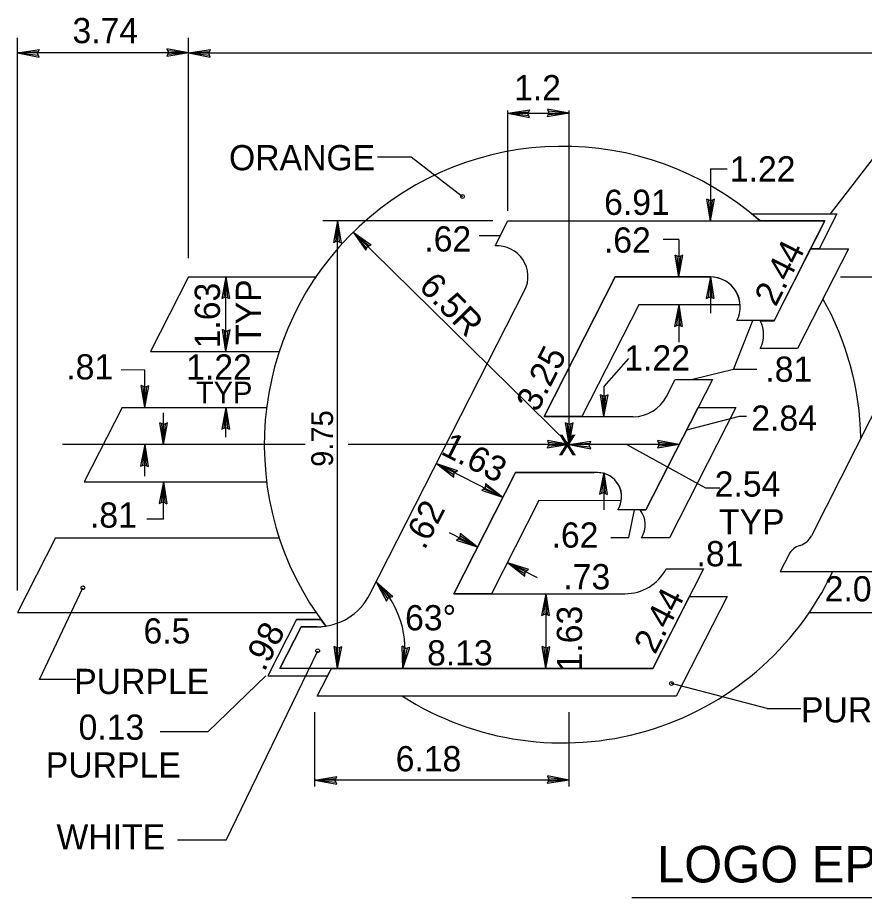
# Model space of a CAD drawing. Extents: x 10268197 to 10269179, y 2141503 to 2142677.
# Drawn here: x 10268592.24 to 10268612.19, y 2142145.29 to 2142166.03 of the extents above; entities that cross this region are included whole.
import ezdxf

# ---------------------------------------------------------------- set-up
doc = ezdxf.new("R2010")
doc.units = 0
for name, color, linetype in [('1', 7, 'Continuous'), ('21', 7, 'Continuous'), ('Default', 7, 'Continuous')]:
    doc.layers.add(name, color=color, linetype=linetype)

msp = doc.modelspace()

# ---------------------------------------------------------------- linework, layer by layer
at = {"layer": '1'}
for p, q in [((10268592.239, 2142152.526), (10268592.239, 2142165.546)), ((10268596.269, 2142160.355), (10268596.269, 2142165.546)), ((10268596.269, 2142165.194), (10268596.782, 2142165.276)), ((10268596.742, 2142165.186), (10268596.782, 2142165.276)), ((10268596.269, 2142165.194), (10268592.239, 2142165.194)), ((10268596.269, 2142165.194), (10268596.761, 2142165.229)), ((10268596.269, 2142165.194), (10268617.622, 2142165.194)), ((10268596.269, 2142165.194), (10268596.779, 2142165.095)), ((10268596.269, 2142165.194), (10268596.76, 2142165.143)), ((10268596.779, 2142165.095), (10268596.742, 2142165.186)), ((10268603.79, 2142163.772), (10268604.305, 2142163.853)), ((10268603.79, 2142161.475), (10268603.79, 2142163.833)), ((10268603.79, 2142163.772), (10268604.283, 2142163.806)), ((10268604.264, 2142163.764), (10268604.305, 2142163.853)), ((10268605.232, 2142155.962), (10268605.232, 2142163.833)), ((10268603.79, 2142163.772), (10268605.232, 2142163.772)), ((10268603.79, 2142163.772), (10268604.301, 2142163.673)), ((10268603.79, 2142163.772), (10268604.282, 2142163.721)), ((10268604.301, 2142163.673), (10268604.264, 2142163.764)), ((10268611.389, 2142161.404), (10268613.109, 2142163.626)), ((10268600.715, 2142162.745), (10268601.51, 2142162.745)), ((10268601.51, 2142162.745), (10268602.722, 2142161.81)), ((10268608.561, 2142162.465), (10268608.561, 2142161.234)), ((10268608.561, 2142162.465), (10268608.959, 2142162.465)), ((10268608.561, 2142161.234), (10268608.48, 2142161.748)), ((10268608.57, 2142161.707), (10268608.48, 2142161.748)), ((10268608.561, 2142161.234), (10268608.527, 2142161.726)), ((10268608.561, 2142161.234), (10268608.661, 2142161.744)), ((10268608.561, 2142161.234), (10268608.613, 2142161.725)), ((10268608.661, 2142161.744), (10268608.57, 2142161.707)), ((10268603.439, 2142161.234), (10268599.428, 2142161.234)), ((10268599.779, 2142161.234), (10268599.68, 2142160.723)), ((10268599.779, 2142161.234), (10268599.728, 2142160.743)), ((10268599.779, 2142150.689), (10268599.779, 2142161.234)), ((10268599.779, 2142161.234), (10268599.86, 2142160.72)), ((10268599.779, 2142161.234), (10268599.813, 2142160.742)), ((10268605.232, 2142155.962), (10268600.148, 2142160.97)), ((10268600.148, 2142160.97), (10268600.571, 2142160.667)), ((10268600.148, 2142160.97), (10268600.443, 2142160.541)), ((10268600.148, 2142160.97), (10268600.462, 2142160.588)), ((10268600.148, 2142160.97), (10268600.523, 2142160.649)), ((10268603.611, 2142160.882), (10268603.111, 2142160.882)), ((10268599.68, 2142160.723), (10268599.771, 2142160.761)), ((10268599.771, 2142160.761), (10268599.86, 2142160.72)), ((10268607.815, 2142160.794), (10268607.45, 2142160.794)), ((10268607.815, 2142160.794), (10268607.815, 2142159.916)), ((10268600.443, 2142160.541), (10268600.48, 2142160.632)), ((10268600.48, 2142160.632), (10268600.571, 2142160.667)), ((10268610.061, 2142158.883), (10268610.924, 2142160.575)), ((10268611.812, 2142160.575), (10268610.614, 2142158.226)), ((10268610.924, 2142160.575), (10268611.812, 2142160.575)), ((10268607.815, 2142159.916), (10268607.733, 2142160.429)), ((10268607.823, 2142160.389), (10268607.733, 2142160.429)), ((10268607.815, 2142159.916), (10268607.781, 2142160.408)), ((10268607.815, 2142159.916), (10268607.914, 2142160.426)), ((10268607.815, 2142159.916), (10268607.866, 2142160.406)), ((10268607.914, 2142160.426), (10268607.823, 2142160.389)), ((10268597.147, 2142159.916), (10268597.048, 2142159.405)), ((10268597.147, 2142159.916), (10268597.096, 2142159.424)), ((10268597.147, 2142158.158), (10268597.147, 2142159.916)), ((10268597.147, 2142159.916), (10268597.229, 2142159.402)), ((10268597.147, 2142159.916), (10268597.182, 2142159.424)), ((10268604.643, 2142156.621), (10268606.322, 2142159.916)), ((10268606.322, 2142159.916), (10268608.561, 2142159.916)), ((10268608.561, 2142159.916), (10268608.462, 2142159.405)), ((10268608.561, 2142159.916), (10268608.51, 2142159.424)), ((10268608.561, 2142159.916), (10268608.643, 2142159.402)), ((10268608.561, 2142159.916), (10268608.596, 2142159.424)), ((10268608.561, 2142159.916), (10268608.561, 2142159.057)), ((10268597.048, 2142159.405), (10268597.139, 2142159.442)), ((10268597.139, 2142159.442), (10268597.229, 2142159.402)), ((10268608.462, 2142159.405), (10268608.553, 2142159.442)), ((10268608.553, 2142159.442), (10268608.643, 2142159.402)), ((10268606.874, 2142159.257), (10268605.531, 2142156.621)), ((10268609.263, 2142159.257), (10268606.874, 2142159.257)), ((10268607.815, 2142159.257), (10268607.716, 2142158.746)), ((10268607.815, 2142159.257), (10268607.764, 2142158.766)), ((10268607.815, 2142159.257), (10268607.815, 2142158.378)), ((10268607.815, 2142159.257), (10268607.897, 2142158.743)), ((10268607.815, 2142159.257), (10268607.85, 2142158.765)), ((10268609.109, 2142157.735), (10268609.56, 2142158.885)), ((10268609.735, 2142158.883), (10268610.061, 2142158.883)), ((10268597.147, 2142158.158), (10268597.066, 2142158.672)), ((10268597.155, 2142158.631), (10268597.066, 2142158.672)), ((10268597.147, 2142158.158), (10268597.112, 2142158.65)), ((10268597.147, 2142158.158), (10268597.247, 2142158.669)), ((10268597.147, 2142158.158), (10268597.199, 2142158.649)), ((10268597.247, 2142158.669), (10268597.155, 2142158.631)), ((10268607.716, 2142158.746), (10268607.807, 2142158.783)), ((10268607.807, 2142158.783), (10268607.897, 2142158.743)), ((10268610.614, 2142158.226), (10268609.735, 2142158.226)), ((10268606.63, 2142157.989), (10268606.051, 2142157.335)), ((10268595.236, 2142157.719), (10268594.679, 2142157.723)), ((10268595.236, 2142156.84), (10268595.236, 2142157.719)), ((10268609.109, 2142157.735), (10268608.142, 2142157.499)), ((10268609.655, 2142157.735), (10268609.109, 2142157.735)), ((10268595.236, 2142156.84), (10268595.154, 2142157.354)), ((10268595.244, 2142157.313), (10268595.154, 2142157.354)), ((10268595.236, 2142156.84), (10268595.201, 2142157.333)), ((10268595.236, 2142156.84), (10268595.335, 2142157.351)), ((10268595.236, 2142156.84), (10268595.287, 2142157.331)), ((10268595.335, 2142157.351), (10268595.244, 2142157.313)), ((10268606.051, 2142157.335), (10268606.051, 2142156.621)), ((10268606.051, 2142156.621), (10268605.969, 2142157.134)), ((10268606.059, 2142157.093), (10268605.969, 2142157.134)), ((10268606.051, 2142156.621), (10268606.016, 2142157.113)), ((10268606.051, 2142156.621), (10268606.15, 2142157.132)), ((10268606.051, 2142156.621), (10268606.102, 2142157.111)), ((10268606.15, 2142157.132), (10268606.059, 2142157.093)), ((10268597.147, 2142156.84), (10268597.048, 2142156.33)), ((10268597.147, 2142156.84), (10268597.096, 2142156.349)), ((10268597.147, 2142156.137), (10268597.147, 2142156.84)), ((10268597.147, 2142156.84), (10268597.229, 2142156.326)), ((10268597.147, 2142156.84), (10268597.182, 2142156.348)), ((10268607.043, 2142154.424), (10268608.274, 2142156.84)), ((10268609.161, 2142156.84), (10268607.595, 2142153.765)), ((10268608.274, 2142156.84), (10268609.161, 2142156.84)), ((10268595.675, 2142155.962), (10268595.675, 2142156.708)), ((10268605.531, 2142156.621), (10268604.643, 2142156.621)), ((10268609.24, 2142156.621), (10268607.999, 2142156.299)), ((10268609.415, 2142156.621), (10268609.24, 2142156.621)), ((10268595.675, 2142155.962), (10268595.594, 2142156.475)), ((10268595.683, 2142156.435), (10268595.594, 2142156.475)), ((10268595.675, 2142155.962), (10268595.641, 2142156.453)), ((10268595.675, 2142155.962), (10268595.774, 2142156.472)), ((10268595.675, 2142155.962), (10268595.726, 2142156.452)), ((10268595.774, 2142156.472), (10268595.683, 2142156.435)), ((10268597.048, 2142156.33), (10268597.139, 2142156.367)), ((10268597.139, 2142156.367), (10268597.229, 2142156.326)), ((10268605.232, 2142155.962), (10268605.15, 2142156.475)), ((10268605.24, 2142156.435), (10268605.15, 2142156.475)), ((10268605.232, 2142155.962), (10268605.197, 2142156.453)), ((10268605.232, 2142155.962), (10268605.33, 2142156.472)), ((10268605.232, 2142155.962), (10268605.283, 2142156.452)), ((10268605.33, 2142156.472), (10268605.24, 2142156.435)), ((10268599.012, 2142155.962), (10268593.295, 2142155.962)), ((10268595.236, 2142155.962), (10268595.137, 2142155.451)), ((10268595.236, 2142155.962), (10268595.184, 2142155.471)), ((10268595.236, 2142155.215), (10268595.236, 2142155.962)), ((10268595.236, 2142155.962), (10268595.317, 2142155.448)), ((10268595.236, 2142155.962), (10268595.27, 2142155.469)), ((10268605.232, 2142155.962), (10268600.025, 2142155.962)), ((10268604.758, 2142155.97), (10268604.717, 2142155.88)), ((10268605.232, 2142155.962), (10268604.717, 2142155.88)), ((10268605.232, 2142155.962), (10268604.721, 2142156.061)), ((10268604.721, 2142156.061), (10268604.758, 2142155.97)), ((10268605.232, 2142155.962), (10268604.74, 2142155.927)), ((10268605.232, 2142155.962), (10268604.741, 2142156.013)), ((10268605.232, 2142155.962), (10268605.745, 2142156.043)), ((10268605.232, 2142155.962), (10268605.724, 2142155.996)), ((10268607.827, 2142155.962), (10268605.232, 2142155.962)), ((10268605.232, 2142155.962), (10268605.742, 2142155.863)), ((10268605.232, 2142155.962), (10268605.722, 2142155.91)), ((10268605.704, 2142155.954), (10268605.745, 2142156.043)), ((10268605.742, 2142155.863), (10268605.704, 2142155.954)), ((10268608.454, 2142154.939), (10268606.584, 2142155.962)), ((10268607.353, 2142155.97), (10268607.313, 2142155.88)), ((10268607.827, 2142155.962), (10268607.313, 2142155.88)), ((10268607.827, 2142155.962), (10268607.316, 2142156.061)), ((10268607.316, 2142156.061), (10268607.353, 2142155.97)), ((10268607.827, 2142155.962), (10268607.334, 2142155.927)), ((10268607.827, 2142155.962), (10268607.335, 2142156.013)), ((10268595.137, 2142155.451), (10268595.228, 2142155.489)), ((10268595.228, 2142155.489), (10268595.317, 2142155.448)), ((10268603.675, 2142154.719), (10268602.108, 2142155.517)), ((10268602.108, 2142155.517), (10268602.603, 2142155.356)), ((10268602.108, 2142155.517), (10268602.518, 2142155.197)), ((10268602.108, 2142155.517), (10268602.522, 2142155.249)), ((10268602.108, 2142155.517), (10268602.562, 2142155.324)), ((10268602.517, 2142152.447), (10268603.972, 2142155.302)), ((10268602.518, 2142155.197), (10268602.526, 2142155.295)), ((10268602.526, 2142155.295), (10268602.603, 2142155.356)), ((10268603.972, 2142155.302), (10268605.817, 2142155.296)), ((10268606.051, 2142155.302), (10268605.952, 2142154.792)), ((10268606.051, 2142155.302), (10268605.999, 2142154.812)), ((10268606.051, 2142155.302), (10268606.132, 2142154.789)), ((10268606.051, 2142155.302), (10268606.085, 2142154.81)), ((10268606.051, 2142155.302), (10268606.051, 2142154.424)), ((10268595.675, 2142155.083), (10268595.576, 2142154.572)), ((10268595.675, 2142155.083), (10268595.624, 2142154.592)), ((10268595.675, 2142154.204), (10268595.675, 2142155.083)), ((10268595.675, 2142155.083), (10268595.757, 2142154.569)), ((10268595.675, 2142155.083), (10268595.709, 2142154.591)), ((10268603.257, 2142154.941), (10268603.179, 2142154.879)), ((10268603.675, 2142154.719), (10268603.179, 2142154.879)), ((10268603.675, 2142154.719), (10268603.22, 2142154.911)), ((10268603.264, 2142155.039), (10268603.257, 2142154.941)), ((10268603.675, 2142154.719), (10268603.26, 2142154.988)), ((10268603.675, 2142154.719), (10268603.264, 2142155.039)), ((10268608.782, 2142154.939), (10268608.454, 2142154.939)), ((10268605.952, 2142154.792), (10268606.043, 2142154.83)), ((10268606.043, 2142154.83), (10268606.132, 2142154.789)), ((10268595.576, 2142154.572), (10268595.667, 2142154.61)), ((10268595.667, 2142154.61), (10268595.757, 2142154.569)), ((10268604.523, 2142154.642), (10268603.404, 2142152.447)), ((10268606.463, 2142154.636), (10268604.523, 2142154.642)), ((10268606.638, 2142153.776), (10268606.77, 2142154.424)), ((10268606.905, 2142154.424), (10268607.043, 2142154.424)), ((10268595.675, 2142154.204), (10268595.286, 2142154.208)), ((10268603.076, 2142153.545), (10268602.413, 2142153.883)), ((10268602.666, 2142153.865), (10268602.658, 2142153.767)), ((10268603.076, 2142153.545), (10268602.666, 2142153.865)), ((10268602.658, 2142153.767), (10268602.581, 2142153.705)), ((10268603.076, 2142153.545), (10268602.581, 2142153.705)), ((10268603.076, 2142153.545), (10268602.622, 2142153.738)), ((10268603.076, 2142153.545), (10268602.662, 2142153.814)), ((10268606.217, 2142153.776), (10268606.638, 2142153.776)), ((10268607.595, 2142153.765), (10268606.936, 2142153.765)), ((10268604.487, 2142152.825), (10268603.78, 2142153.185)), ((10268603.78, 2142153.185), (10268604.275, 2142153.024)), ((10268603.78, 2142153.185), (10268604.19, 2142152.865)), ((10268603.78, 2142153.185), (10268604.195, 2142152.916)), ((10268603.78, 2142153.185), (10268604.234, 2142152.993)), ((10268604.198, 2142152.963), (10268604.275, 2142153.024)), ((10268604.19, 2142152.865), (10268604.198, 2142152.963)), ((10268592.754, 2142150.424), (10268593.777, 2142152.589)), ((10268600.689, 2142152.731), (10268601.077, 2142152.384)), ((10268600.689, 2142152.731), (10268600.934, 2142152.272)), ((10268600.689, 2142152.731), (10268600.959, 2142152.317)), ((10268600.689, 2142152.731), (10268601.027, 2142152.371)), ((10268600.981, 2142152.359), (10268601.077, 2142152.384)), ((10268603.404, 2142152.447), (10268602.517, 2142152.447)), ((10268604.683, 2142152.447), (10268604.584, 2142151.936)), ((10268604.683, 2142152.447), (10268604.632, 2142151.956)), ((10268604.683, 2142152.447), (10268604.683, 2142150.689)), ((10268604.683, 2142152.447), (10268604.765, 2142151.933)), ((10268604.683, 2142152.447), (10268604.717, 2142151.955)), ((10268607.205, 2142150.689), (10268608.066, 2142152.379)), ((10268608.954, 2142152.379), (10268607.757, 2142150.03)), ((10268608.066, 2142152.379), (10268608.954, 2142152.379)), ((10268600.934, 2142152.272), (10268600.981, 2142152.359)), ((10268604.584, 2142151.936), (10268604.676, 2142151.974)), ((10268604.676, 2142151.974), (10268604.765, 2142151.933)), ((10268599.779, 2142150.689), (10268599.697, 2142151.203)), ((10268599.787, 2142151.162), (10268599.697, 2142151.203)), ((10268599.779, 2142150.689), (10268599.744, 2142151.181)), ((10268599.779, 2142150.689), (10268599.878, 2142151.2)), ((10268599.779, 2142150.689), (10268599.83, 2142151.18)), ((10268599.878, 2142151.2), (10268599.787, 2142151.162)), ((10268601.317, 2142150.689), (10268601.299, 2142151.209)), ((10268601.383, 2142151.158), (10268601.299, 2142151.209)), ((10268601.317, 2142150.689), (10268601.478, 2142151.184)), ((10268601.317, 2142150.689), (10268601.343, 2142151.182)), ((10268601.317, 2142150.689), (10268601.427, 2142151.171)), ((10268601.478, 2142151.184), (10268601.383, 2142151.158)), ((10268604.683, 2142150.689), (10268604.601, 2142151.203)), ((10268604.691, 2142151.162), (10268604.601, 2142151.203)), ((10268604.683, 2142150.689), (10268604.649, 2142151.181)), ((10268604.683, 2142150.689), (10268604.782, 2142151.2)), ((10268604.683, 2142150.689), (10268604.734, 2142151.18)), ((10268604.782, 2142151.2), (10268604.691, 2142151.162)), ((10268597.156, 2142146.641), (10268599.309, 2142151.104)), ((10268596.73, 2142149.2), (10268598.084, 2142150.513)), ((10268599.297, 2142150.03), (10268599.633, 2142150.689)), ((10268599.633, 2142150.689), (10268607.205, 2142150.689)), ((10268593.61, 2142150.424), (10268592.754, 2142150.424)), ((10268609.901, 2142149.741), (10268607.645, 2142150.331)), ((10268607.757, 2142150.03), (10268599.297, 2142150.03)), ((10268609.901, 2142149.741), (10268610.696, 2142149.741)), ((10268599.246, 2142147.908), (10268599.246, 2142149.653)), ((10268605.232, 2142147.908), (10268605.232, 2142149.653)), ((10268595.595, 2142149.2), (10268596.73, 2142149.2)), ((10268605.232, 2142148.056), (10268599.246, 2142148.056)), ((10268596.005, 2142146.649), (10268597.156, 2142146.649))]:
    msp.add_line(p, q, dxfattribs=at)
msp.add_lwpolyline([(10268609.53, 2142161.404), (10268611.544, 2142161.404), (10268611.122, 2142160.575), (10268610.924, 2142160.575), (10268611.26, 2142161.234), (10268609.73, 2142161.234)], close=True, dxfattribs=at)
for centre in [(10268602.722, 2142161.81), (10268593.777, 2142152.589), (10268599.309, 2142151.104), (10268607.645, 2142150.331)]:
    msp.add_circle(centre, 0.0439, dxfattribs=at)
for centre, radius, start, end in [((10268608.562, 2142159.213), 0.703, 3.5833, 90), ((10268609.113, 2142158.554), 0.703, 332.2089, 27.9127), ((10268605.9, 2142154.732), 0.571, 350.3502, 98.3344), ((10268606.455, 2142154.073), 0.571, 327.421, 37.9799), ((10268599.168, 2142151.145), 2.197, 348.03, 46.2026)]:
    msp.add_arc(centre, radius, start, end, dxfattribs=at)
at = {"layer": '21'}
for p, q in [((10268592.239, 2142165.194), (10268592.753, 2142165.276)), ((10268592.712, 2142165.186), (10268592.753, 2142165.276)), ((10268596.269, 2142165.194), (10268595.758, 2142165.293)), ((10268595.758, 2142165.293), (10268595.795, 2142165.203)), ((10268596.269, 2142165.194), (10268595.778, 2142165.246)), ((10268592.239, 2142165.194), (10268592.732, 2142165.229)), ((10268592.239, 2142165.194), (10268592.75, 2142165.095)), ((10268592.239, 2142165.194), (10268592.73, 2142165.143)), ((10268592.75, 2142165.095), (10268592.712, 2142165.186)), ((10268595.795, 2142165.203), (10268595.755, 2142165.112)), ((10268596.269, 2142165.194), (10268595.755, 2142165.112)), ((10268596.269, 2142165.194), (10268595.777, 2142165.16)), ((10268605.232, 2142163.772), (10268604.721, 2142163.871)), ((10268604.721, 2142163.871), (10268604.758, 2142163.78)), ((10268605.232, 2142163.772), (10268604.741, 2142163.823)), ((10268604.758, 2142163.78), (10268604.717, 2142163.69)), ((10268605.232, 2142163.772), (10268604.717, 2142163.69)), ((10268605.232, 2142163.772), (10268604.74, 2142163.737)), ((10268599.246, 2142148.056), (10268599.76, 2142148.138)), ((10268599.246, 2142148.056), (10268599.739, 2142148.091)), ((10268599.246, 2142148.056), (10268599.757, 2142147.957)), ((10268599.246, 2142148.056), (10268599.738, 2142148.005)), ((10268599.72, 2142148.049), (10268599.76, 2142148.138)), ((10268599.757, 2142147.957), (10268599.72, 2142148.049)), ((10268604.758, 2142148.064), (10268604.718, 2142147.975)), ((10268605.232, 2142148.056), (10268604.718, 2142147.975)), ((10268605.232, 2142148.056), (10268604.721, 2142148.155)), ((10268604.721, 2142148.155), (10268604.758, 2142148.064)), ((10268605.232, 2142148.056), (10268604.74, 2142148.022)), ((10268605.232, 2142148.056), (10268604.741, 2142148.108)), ((10268606.71, 2142145.291), (10268616.551, 2142145.291))]:
    msp.add_line(p, q, dxfattribs=at)
at = {"layer": 'Default'}
for p, q in [((10268609.53, 2142161.404), (10268611.544, 2142161.404)), ((10268611.544, 2142161.404), (10268611.122, 2142160.575)), ((10268603.491, 2142160.645), (10268603.79, 2142161.234)), ((10268603.79, 2142161.234), (10268611.26, 2142161.234)), ((10268611.26, 2142161.234), (10268610.063, 2142158.885)), ((10268610.061, 2142158.883), (10268610.924, 2142160.575)), ((10268611.812, 2142160.575), (10268610.614, 2142158.226)), ((10268610.924, 2142160.575), (10268611.812, 2142160.575)), ((10268596.269, 2142159.916), (10268595.373, 2142158.158)), ((10268596.269, 2142159.916), (10268599.268, 2142159.916)), ((10268606.322, 2142159.916), (10268604.643, 2142156.621)), ((10268604.643, 2142156.621), (10268606.322, 2142159.916)), ((10268608.561, 2142159.916), (10268606.322, 2142159.916)), ((10268606.322, 2142159.916), (10268608.561, 2142159.916)), ((10268611.626, 2142159.916), (10268636.689, 2142159.916)), ((10268600.538, 2142152.436), (10268604.184, 2142159.592)), ((10268606.874, 2142159.257), (10268605.531, 2142156.621)), ((10268609.263, 2142159.257), (10268606.874, 2142159.257)), ((10268610.063, 2142158.885), (10268609.184, 2142158.885)), ((10268609.735, 2142158.883), (10268610.061, 2142158.883)), ((10268610.614, 2142158.226), (10268609.735, 2142158.226)), ((10268595.373, 2142158.158), (10268598.403, 2142158.158)), ((10268613.116, 2142158.113), (10268610.941, 2142153.811)), ((10268608.61, 2142157.499), (10268607.043, 2142154.424)), ((10268607.527, 2142157.1), (10268607.731, 2142157.499)), ((10268607.731, 2142157.499), (10268608.61, 2142157.499)), ((10268594.702, 2142156.84), (10268593.806, 2142155.083)), ((10268594.702, 2142156.84), (10268598.106, 2142156.84)), ((10268607.043, 2142154.424), (10268608.274, 2142156.84)), ((10268609.161, 2142156.84), (10268607.595, 2142153.765)), ((10268608.274, 2142156.84), (10268609.161, 2142156.84)), ((10268604.643, 2142156.621), (10268606.745, 2142156.621)), ((10268605.531, 2142156.621), (10268604.643, 2142156.621)), ((10268603.972, 2142155.302), (10268602.517, 2142152.447)), ((10268602.517, 2142152.447), (10268603.972, 2142155.302)), ((10268605.9, 2142155.302), (10268603.972, 2142155.302)), ((10268603.972, 2142155.302), (10268605.817, 2142155.296)), ((10268593.806, 2142155.083), (10268598.106, 2142155.083)), ((10268604.523, 2142154.642), (10268603.404, 2142152.447)), ((10268606.463, 2142154.636), (10268604.523, 2142154.642)), ((10268607.043, 2142154.424), (10268606.381, 2142154.424)), ((10268606.905, 2142154.424), (10268607.043, 2142154.424)), ((10268593.135, 2142153.765), (10268592.239, 2142152.007)), ((10268593.135, 2142153.765), (10268598.403, 2142153.765)), ((10268607.595, 2142153.765), (10268606.936, 2142153.765)), ((10268610.406, 2142153.364), (10268610.209, 2142152.974)), ((10268608.402, 2142153.038), (10268607.205, 2142150.689)), ((10268607.523, 2142153.038), (10268608.402, 2142153.038)), ((10268610.209, 2142152.974), (10268612.405, 2142152.974)), ((10268602.517, 2142152.447), (10268606.548, 2142152.447)), ((10268603.404, 2142152.447), (10268602.517, 2142152.447)), ((10268607.205, 2142150.689), (10268608.066, 2142152.379)), ((10268608.954, 2142152.379), (10268607.757, 2142150.03)), ((10268608.066, 2142152.379), (10268608.954, 2142152.379)), ((10268592.239, 2142152.007), (10268599.268, 2142152.007)), ((10268610.892, 2142152.007), (10268632.66, 2142152.007)), ((10268598.809, 2142151.844), (10268598.132, 2142150.513)), ((10268598.809, 2142151.844), (10268599.383, 2142151.844)), ((10268598.419, 2142150.689), (10268598.917, 2142151.668)), ((10268598.917, 2142151.668), (10268598.419, 2142150.689)), ((10268598.917, 2142151.668), (10268599.286, 2142151.668)), ((10268599.286, 2142151.668), (10268598.917, 2142151.668)), ((10268598.132, 2142150.513), (10268599.543, 2142150.513)), ((10268607.205, 2142150.689), (10268598.419, 2142150.689)), ((10268599.297, 2142150.03), (10268599.633, 2142150.689)), ((10268599.633, 2142150.689), (10268607.205, 2142150.689)), ((10268607.757, 2142150.03), (10268599.297, 2142150.03))]:
    msp.add_line(p, q, dxfattribs=at)
msp.add_lwpolyline([(10268599.383, 2142151.844), (10268598.809, 2142151.844), (10268598.132, 2142150.513), (10268599.543, 2142150.513), (10268599.633, 2142150.689), (10268598.419, 2142150.689), (10268598.917, 2142151.668), (10268599.286, 2142151.668), (10268599.502, 2142151.685)], close=True, dxfattribs=at)
for centre, radius, start, end in [((10268605.081, 2142155.962), 7.03, 48.5904, 217.4725), ((10268603.539, 2142159.922), 0.725, 332.9998, 93.8045), ((10268608.562, 2142159.213), 0.703, 332.2089, 90), ((10268608.562, 2142159.213), 0.703, 3.5833, 90), ((10268605.081, 2142155.962), 7.03, 1.2967, 29.2778), ((10268609.113, 2142158.554), 0.703, 332.2089, 27.9127), ((10268606.745, 2142157.499), 0.879, 270, 332.9883), ((10268605.9, 2142154.732), 0.571, 350.3502, 98.3344), ((10268605.9, 2142154.732), 0.571, 327.421, 90), ((10268606.455, 2142154.073), 0.571, 327.421, 37.9799), ((10268606.548, 2142153.545), 1.098, 270, 332.5096), ((10268605.081, 2142155.962), 7.03, 237.5383, 334.8493), ((10268599.286, 2142153.074), 1.406, 270, 332.9991)]:
    msp.add_arc(centre, radius, start, end, dxfattribs=at)
for centre, start_param, end_param in [((10268610.549, 2142154.012), 0.286787, 1.099486), ((10268610.798, 2142153.163), 3.428379, 4.240701)]:
    msp.add_ellipse(centre, major_axis=(0, -0.443), ratio=0.992614, start_param=start_param, end_param=end_param, dxfattribs=at)

# ---------------------------------------------------------------- texts
at = {"layer": '1'}
for s, height, p in [('3.74', 0.5942, (10268593.532, 2142165.423)), ('1.2', 0.5942, (10268603.936, 2142164.077)), ('ORANGE', 0.5942, (10268597.22, 2142162.428)), ('1.22', 0.5942, (10268609.02, 2142162.163)), ('6.91', 0.5942, (10268606.058, 2142161.376)), ('.62', 0.5942, (10268601.822, 2142160.513)), ('.62', 0.5942, (10268606.053, 2142160.487)), ('1.22', 0.5942, (10268606.534, 2142157.708)), ('.81', 0.5942, (10268593.386, 2142157.498)), ('1.22', 0.5942, (10268596.212, 2142157.495)), ('.81', 0.5942, (10268609.856, 2142157.443)), ('TYP', 0.5125, (10268596.439, 2142156.934)), ('2.84', 0.5942, (10268609.525, 2142156.29)), ('x', 0.641, (10268604.978, 2142155.706)), ('2.54', 0.5942, (10268608.664, 2142154.737)), ('.81', 0.5942, (10268593.944, 2142154.005)), ('TYP', 0.5942, (10268608.764, 2142153.846)), ('.62', 0.5942, (10268604.82, 2142153.534)), ('.81', 0.5942, (10268608.235, 2142153.095)), ('.73', 0.5942, (10268605.098, 2142152.552)), ('2.03', 0.5942, (10268611.255, 2142152.267)), ('63°', 0.5942, (10268601.368, 2142151.585)), ('6.5', 0.5942, (10268595.205, 2142151.275)), ('8.13', 0.5942, (10268601.887, 2142150.757)), ('PURPLE', 0.5942, (10268593.574, 2142150.084)), ('PURPLE', 0.5942, (10268610.695, 2142149.416)), ('0.13', 0.5942, (10268593.676, 2142149.007)), ('6.18', 0.5942, (10268601.147, 2142148.263)), ('PURPLE', 0.5942, (10268592.904, 2142148.115)), ('WHITE', 0.5942, (10268593.156, 2142146.422)), ('LOGO EP-6.5R', 0.86053, (10268607.305, 2142145.644))]:
    msp.add_text(s, height=height, dxfattribs=at).set_placement(p)
for s, height, rotation, p in [('2.44', 0.5942, 63, (10268610.101, 2142159.19)), ('6.5R', 0.5942, 314.1812, (10268601.667, 2142159.664)), ('1.63', 0.5942, 90, (10268597.007, 2142158.231)), ('TYP', 0.5942, 90, (10268597.975, 2142158.311)), ('3.25', 0.5942, 63.0402, (10268604.486, 2142156.702)), ('9.75', 0.5125, 90, (10268599.671, 2142155.438)), ('1.63', 0.5942, 332.9866, (10268602.182, 2142155.751)), ('.62', 0.5942, 63.0402, (10268601.827, 2142153.46)), ('2.44', 0.5942, 63, (10268607.26, 2142150.998)), ('1.63', 0.5942, 90, (10268605.538, 2142150.617)), ('.98', 0.5942, 63, (10268598.055, 2142150.592))]:
    msp.add_text(s, height=height, rotation=rotation, dxfattribs=at).set_placement(p)

doc.saveas('drawing.dxf')
